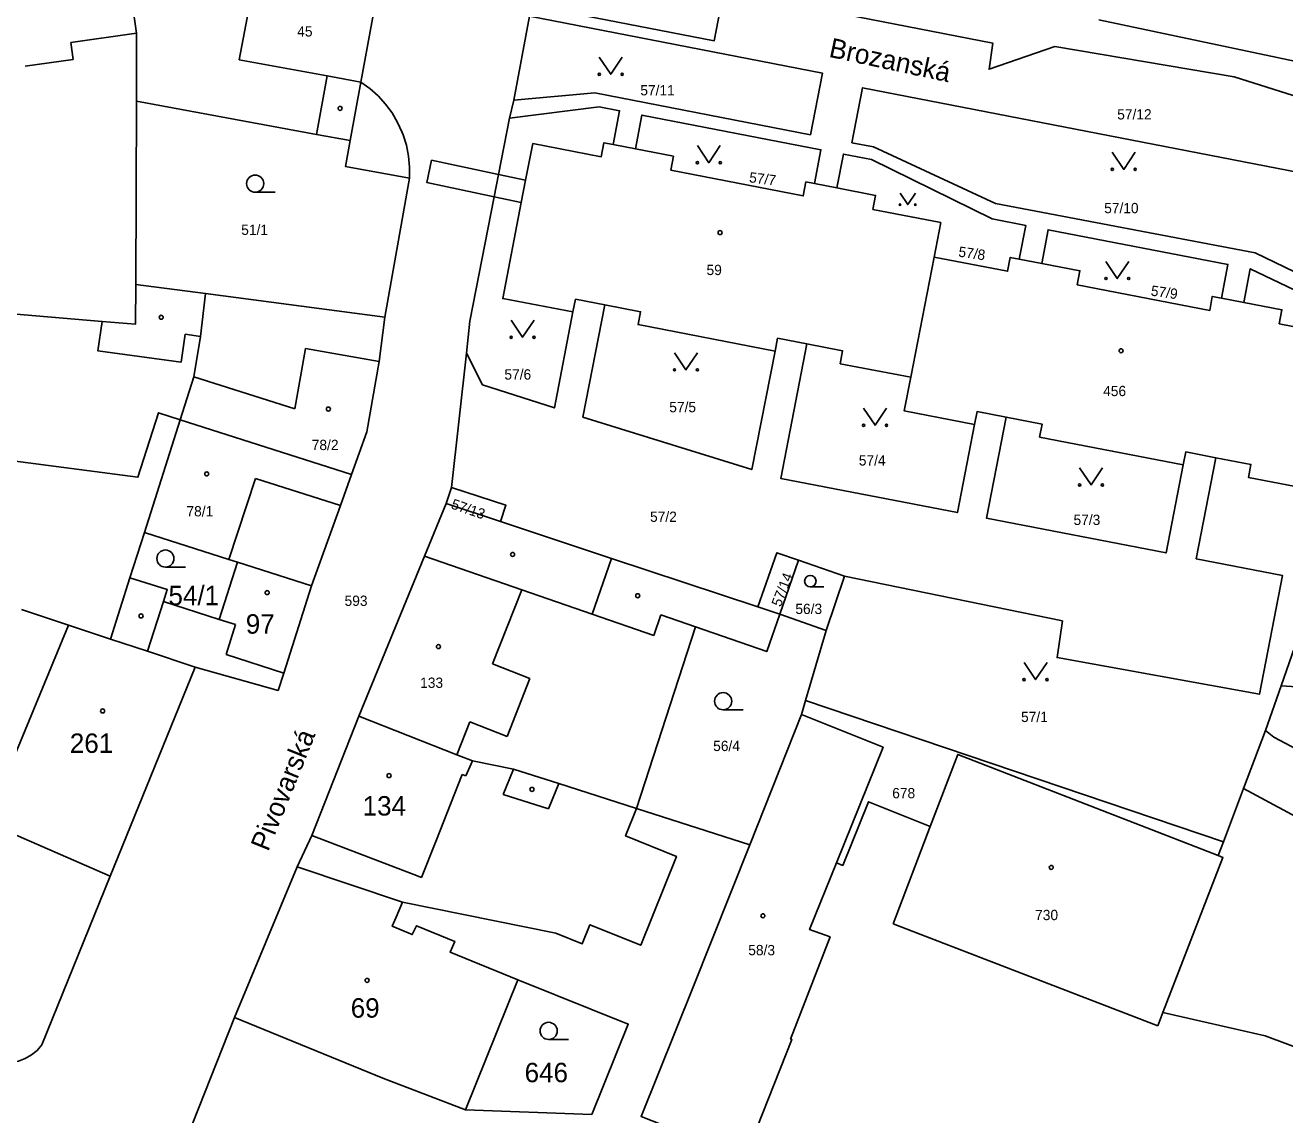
# Model space of a CAD drawing. Extents: x -758582 to -751794, y -998770 to -994350.
# Drawn here: x -755710.1 to -755599.9, y -995827 to -995731.7 of the extents above; entities that cross this region are included whole.
import ezdxf

# ---------------------------------------------------------------- set-up
doc = ezdxf.new("R2010")
doc.units = 0
for name, color, linetype in [('Hranice parcel', 7, 'Continuous'), ('Parcelní čísla', 7, 'Continuous'), ('Pop  PČ popisy', 7, 'Continuous'), ('Vnitřní kresba', 7, 'Continuous'), ('Věcná břemena k části', 7, 'Continuous'), ('Značky budov', 7, 'Continuous'), ('Značky kultur', 7, 'Continuous')]:
    doc.layers.add(name, color=color, linetype=linetype)

msp = doc.modelspace()

# ---------------------------------------------------------------- linework, layer by layer
at = {"layer": 'Hranice parcel'}
for p, q in [((-755680.76, -995736.69), (-755679.1, -995727.64)), ((-755666.01, -995730.92), (-755667.39, -995738.27)), ((-755700.44, -995754.38), (-755700.4, -995738.36)), ((-755667.39, -995738.27), (-755667.76, -995739.85)), ((-755656.75, -995742.53), (-755658.71, -995742.14)), ((-755678.66, -995757.24), (-755676.51, -995745.09)), ((-755639.13, -995745.94), (-755641.09, -995745.56)), ((-755632.66, -995762.51), (-755630.63, -995752)), ((-755621.21, -995752.55), (-755623.18, -995752.17)), ((-755603.54, -995755.96), (-755605.5, -995755.58)), ((-755715.41, -995756.62), (-755703.4, -995757.63)), ((-755671.53, -995760.39), (-755672.83, -995772.14)), ((-755696.56, -995766.23), (-755699.7, -995776.09)), ((-755681.58, -995771.01), (-755696.56, -995766.23)), ((-755673.3, -995773.56), (-755672.83, -995772.14)), ((-755668.55, -995775.13), (-755673.3, -995773.56)), ((-755700.96, -995780.05), (-755699.7, -995776.09)), ((-755691.55, -995778.69), (-755685.07, -995780.76)), ((-755642.49, -995778.52), (-755644.13, -995783.24)), ((-755638.45, -995779.92), (-755642.49, -995778.52)), ((-755596.45, -995778.47), (-755600.27, -995789.5)), ((-755700.96, -995780.05), (-755702.67, -995785.41)), ((-755640.06, -995784.65), (-755638.45, -995779.92)), ((-755644.13, -995783.24), (-755646.04, -995782.58)), ((-755644.13, -995783.24), (-755640.06, -995784.65)), ((-755641.86, -995790.79), (-755640.06, -995784.65)), ((-755702.69, -995806.16), (-755695.27, -995787.86)), ((-755601.63, -995793.41), (-755600.27, -995789.5)), ((-755642.21, -995792), (-755641.86, -995790.79)), ((-755641.86, -995790.79), (-755605.32, -995803.16)), ((-755642.21, -995792), (-755646.75, -995803.42)), ((-755603.55, -995798.48), (-755601.63, -995793.41)), ((-755605.32, -995803.16), (-755603.55, -995798.48)), ((-755584.98, -995808.56), (-755603.55, -995798.48)), ((-755646.75, -995803.42), (-755656.65, -995800.23)), ((-755634.2, -995810.32), (-755630.97, -995801.82)), ((-755605.32, -995803.16), (-755605.77, -995804.36)), ((-755686.35, -995805.35), (-755691.81, -995818.51)), ((-755677.13, -995808.42), (-755686.35, -995805.35)), ((-755708.67, -995820.92), (-755702.69, -995806.16)), ((-755611.06, -995819.25), (-755634.2, -995810.32)), ((-755671.62, -995826.6), (-755667.03, -995815.21)), ((-755610.61, -995818.09), (-755611.06, -995819.25))]:
    msp.add_line(p, q, dxfattribs=at)
for points in [[(-755616.22, -995731.24), (-755584.47, -995737.95), (-755577.34, -995717.51)], [(-755701.66, -995723.31), (-755700.39, -995732.42), (-755700.4, -995738.36)], [(-755580.66, -995748.82), (-755579.74, -995745.65), (-755585.82, -995744.38), (-755590.08, -995740.75), (-755604.38, -995736.24), (-755620.07, -995733.57), (-755625.82, -995735.56), (-755625.48, -995733.29), (-755649.01, -995728.69), (-755649.85, -995733.07), (-755665.81, -995729.99)], [(-755667.39, -995738.27), (-755660.29, -995737.63), (-755641.44, -995741.29), (-755640.39, -995735.9), (-755666.01, -995730.92)], [(-755676.51, -995745.09), (-755676.5, -995744.12), (-755676.59, -995743.16), (-755676.78, -995742.22), (-755677.07, -995741.29), (-755677.14, -995741.1), (-755677.55, -995740.22), (-755678.03, -995739.39), (-755678.61, -995738.61), (-755679.26, -995737.9), (-755679.98, -995737.26), (-755680.76, -995736.69)], [(-755594.4, -995748.74), (-755593.78, -995745.56), (-755636.88, -995737.19), (-755637.81, -995742), (-755635.94, -995742.36), (-755625.25, -995747.31), (-755602.55, -995751.62), (-755595.59, -995754.97), (-755595.48, -995754.29)], [(-755700.4, -995738.36), (-755684.65, -995741.26), (-755681.7, -995741.8), (-755682.11, -995744.07), (-755676.51, -995745.09)], [(-755658.71, -995742.14), (-755658.14, -995739.2), (-755659.91, -995738.86), (-755667.76, -995739.85)], [(-755641.09, -995745.56), (-755640.52, -995742.61), (-755656.18, -995739.58), (-755656.75, -995742.53)], [(-755667.76, -995739.85), (-755668.72, -995744.76), (-755669.1, -995746.72), (-755671.22, -995757.61), (-755671.53, -995760.39)], [(-755658.71, -995742.14), (-755659.5, -995741.99), (-755659.74, -995743.22), (-755665.73, -995742.06), (-755666.35, -995745.26), (-755666.73, -995747.23), (-755668.35, -995755.62), (-755662.21, -995756.8)], [(-755641.09, -995745.56), (-755641.83, -995745.42), (-755642.07, -995746.65), (-755653.65, -995744.4), (-755653.42, -995743.17), (-755656.75, -995742.53)], [(-755623.18, -995752.17), (-755622.61, -995749.23), (-755625.55, -995748.66), (-755636.1, -995743.45), (-755638.56, -995742.98), (-755639.13, -995745.94)], [(-755630.63, -995752), (-755630.05, -995748.98), (-755635.98, -995747.83), (-755635.74, -995746.6), (-755639.13, -995745.94)], [(-755580.66, -995748.82), (-755587.69, -995757.83), (-755595.9, -995756.4), (-755602.97, -995753.01), (-755603.54, -995755.96)], [(-755605.5, -995755.58), (-755604.93, -995752.64), (-755620.65, -995749.6), (-755621.21, -995752.55)], [(-755623.18, -995752.17), (-755623.96, -995752.02), (-755624.2, -995753.24), (-755630.63, -995752)], [(-755605.5, -995755.58), (-755606.29, -995755.43), (-755606.52, -995756.66), (-755618.11, -995754.42), (-755617.87, -995753.19), (-755621.21, -995752.55)], [(-755700.44, -995754.38), (-755700.48, -995757.87), (-755703.4, -995757.63)], [(-755678.66, -995757.24), (-755694.34, -995755.18), (-755700.44, -995754.38)], [(-755662.21, -995756.8), (-755661.99, -995755.68), (-755659.44, -995756.17)], [(-755605.98, -995769.55), (-755602.92, -995770.14), (-755603.13, -995771.27), (-755597.04, -995772.44), (-755594.45, -995758.99), (-755600.44, -995757.83), (-755600.2, -995756.61), (-755603.54, -995755.96)], [(-755681.58, -995771.01), (-755680.25, -995767.29), (-755679.16, -995761.13), (-755678.66, -995757.24)], [(-755662.21, -995756.8), (-755663.83, -995765.19), (-755670.12, -995763.18), (-755671.53, -995760.39)], [(-755644.54, -995760.22), (-755646.57, -995770.58), (-755661.34, -995765.99), (-755659.44, -995756.17)], [(-755659.44, -995756.17), (-755656.3, -995756.78), (-755656.52, -995757.9), (-755644.54, -995760.22)], [(-755703.4, -995757.63), (-755703.76, -995760.2), (-755696.49, -995761.18), (-755696.12, -995758.75), (-755694.8, -995758.93)], [(-755694.8, -995758.93), (-755695.36, -995762.47), (-755696.56, -995766.23)], [(-755644.54, -995760.22), (-755644.32, -995759.09), (-755641.77, -995759.58)], [(-755627.09, -995766.64), (-755628.58, -995774.35), (-755644.04, -995771.36), (-755641.77, -995759.58)], [(-755641.77, -995759.58), (-755638.63, -995760.19), (-755638.84, -995761.32), (-755632.66, -995762.51)], [(-755632.66, -995762.51), (-755633.23, -995765.46), (-755627.09, -995766.64)], [(-755728.64, -995767.54), (-755700.26, -995771.25), (-755698.47, -995765.62), (-755696.56, -995766.23)], [(-755627.09, -995766.64), (-755626.87, -995765.51), (-755624.32, -995766)], [(-755608.83, -995770.17), (-755610.33, -995777.87), (-755626.04, -995774.84), (-755624.32, -995766)], [(-755624.32, -995766), (-755621.18, -995766.61), (-755621.4, -995767.74), (-755615.05, -995768.96), (-755608.83, -995770.17)], [(-755608.83, -995770.17), (-755608.61, -995769.04), (-755605.98, -995769.55)], [(-755605.98, -995769.55), (-755607.7, -995778.38), (-755600.16, -995779.85), (-755602.17, -995790.24), (-755619.87, -995787.03), (-755619.4, -995783.82), (-755638.45, -995779.92)], [(-755685.07, -995780.76), (-755682.56, -995773.74), (-755681.58, -995771.01)], [(-755672.83, -995772.14), (-755668.08, -995773.71), (-755668.55, -995775.13)], [(-755673.3, -995773.56), (-755675.19, -995778.16), (-755680.93, -995792.16)], [(-755646.04, -995782.58), (-755658.84, -995778.35), (-755668.55, -995775.13)], [(-755699.7, -995776.09), (-755692.31, -995778.45), (-755691.55, -995778.69)], [(-755646.04, -995782.58), (-755644.38, -995777.86), (-755642.49, -995778.52)], [(-755691.55, -995778.69), (-755693.15, -995783.69), (-755698.03, -995782.13), (-755697.7, -995781.09), (-755700.96, -995780.05)], [(-755695.27, -995787.86), (-755688, -995789.91), (-755687.51, -995788.39), (-755685.07, -995780.76)], [(-755702.67, -995785.41), (-755706.35, -995784.19), (-755710.44, -995782.83)], [(-755656.65, -995800.23), (-755651.49, -995784.34), (-755645.26, -995786.5), (-755644.13, -995783.24)], [(-755702.67, -995785.41), (-755699.42, -995786.48), (-755695.27, -995787.86)], [(-755600.27, -995789.5), (-755593.92, -995789.92), (-755582.21, -995803.41)], [(-755680.93, -995792.16), (-755685.05, -995802.61), (-755686.35, -995805.35)], [(-755680.93, -995792.16), (-755672.37, -995795.53), (-755671.01, -995796.07), (-755667.41, -995796.78), (-755663.44, -995798.04), (-755656.65, -995800.23)], [(-755639.17, -995804.99), (-755635.09, -995794.87), (-755642.21, -995792)], [(-755601.63, -995793.41), (-755600.92, -995793.98), (-755591.16, -995799.16), (-755582.21, -995803.41)], [(-755630.97, -995801.82), (-755628.56, -995795.51), (-755605.77, -995804.36)], [(-755702.69, -995806.16), (-755713.48, -995801.46), (-755717.47, -995799.72)], [(-755630.97, -995801.82), (-755636.37, -995799.65), (-755638.61, -995805.21), (-755639.17, -995804.99)], [(-755656.65, -995800.23), (-755657.61, -995802.63), (-755653.16, -995804.42), (-755656.28, -995812.2), (-755660.74, -995810.42), (-755661.4, -995812.07), (-755663.72, -995811.14), (-755677.13, -995808.42)], [(-755646.75, -995803.42), (-755651.74, -995815.92), (-755656.25, -995827.17), (-755647.14, -995830.77), (-755643.06, -995820.45), (-755643.18, -995820.41), (-755639.72, -995811.47), (-755641.52, -995810.83), (-755639.17, -995804.99)], [(-755605.77, -995804.36), (-755605.37, -995804.51), (-755610.61, -995818.09)], [(-755677.13, -995808.42), (-755677.67, -995809.73), (-755678.02, -995810.54), (-755676.27, -995811.27), (-755675.9, -995810.49), (-755672.56, -995811.86), (-755672.96, -995812.81), (-755667.03, -995815.21)], [(-755667.03, -995815.21), (-755657.38, -995819.09), (-755660.57, -995827.01), (-755671.62, -995826.6)], [(-755691.81, -995818.51), (-755696.52, -995830.39), (-755697.31, -995832.34)], [(-755671.62, -995826.6), (-755678.83, -995823.83), (-755691.81, -995818.51)], [(-755586.26, -995825.88), (-755601.67, -995820.12), (-755610.61, -995818.09)], [(-755712.85, -995822.36), (-755712.23, -995822.47), (-755711.6, -995822.49), (-755710.98, -995822.4), (-755710.71, -995822.33), (-755710.12, -995822.1), (-755709.58, -995821.79), (-755709.09, -995821.39), (-755708.67, -995820.92)]]:
    msp.add_lwpolyline(points, dxfattribs=at)
at = {"layer": 'Vnitřní kresba'}
for p, q in [((-755691.41, -995734.74), (-755689.66, -995725.61)), ((-755700.39, -995732.42), (-755706.13, -995733.22)), ((-755706.13, -995733.22), (-755705.93, -995734.71)), ((-755705.93, -995734.71), (-755710.14, -995735.29)), ((-755691.41, -995734.74), (-755683.71, -995736.15)), ((-755683.71, -995736.15), (-755684.65, -995741.26)), ((-755683.71, -995736.15), (-755680.76, -995736.69)), ((-755681.7, -995741.8), (-755680.76, -995736.69)), ((-755694.8, -995758.93), (-755694.34, -995755.18)), ((-755686.55, -995765.28), (-755685.61, -995759.99)), ((-755679.16, -995761.13), (-755685.61, -995759.99)), ((-755695.36, -995762.47), (-755686.55, -995765.28)), ((-755689.99, -995771.37), (-755692.31, -995778.45)), ((-755682.56, -995773.74), (-755689.99, -995771.37)), ((-755675.19, -995778.16), (-755666.68, -995781.1)), ((-755658.84, -995778.35), (-755660.53, -995783.23)), ((-755669.24, -995787.58), (-755666.68, -995781.1)), ((-755666.68, -995781.1), (-755660.53, -995783.23)), ((-755699.42, -995786.48), (-755698.03, -995782.13)), ((-755660.53, -995783.23), (-755655.14, -995785.1)), ((-755655.14, -995785.1), (-755654.52, -995783.3)), ((-755654.52, -995783.3), (-755651.49, -995784.34)), ((-755713.48, -995801.46), (-755706.35, -995784.19)), ((-755693.15, -995783.69), (-755691.72, -995784.15)), ((-755691.72, -995784.15), (-755692.56, -995786.77)), ((-755692.56, -995786.77), (-755687.51, -995788.39)), ((-755665.98, -995788.86), (-755669.24, -995787.58)), ((-755667.98, -995793.93), (-755665.98, -995788.86)), ((-755672.37, -995795.53), (-755671.23, -995792.65)), ((-755671.23, -995792.65), (-755667.98, -995793.93)), ((-755671.59, -995797.37), (-755671.01, -995796.07)), ((-755668.32, -995799.02), (-755667.41, -995796.78)), ((-755671.91, -995797.25), (-755674.22, -995803.13)), ((-755671.91, -995797.25), (-755671.59, -995797.37)), ((-755668.32, -995799.02), (-755664.34, -995800.27)), ((-755663.44, -995798.04), (-755664.34, -995800.27)), ((-755685.05, -995802.61), (-755676.13, -995806.02)), ((-755674.22, -995803.13), (-755675.47, -995806.28)), ((-755676.13, -995806.02), (-755675.47, -995806.28))]:
    msp.add_line(p, q, dxfattribs=at)
at = {"layer": 'Věcná břemena k části'}
msp.add_lwpolyline([(-755674.58, -995743.51), (-755675, -995745.46), (-755669.1, -995746.72), (-755666.73, -995747.23), (-755666.35, -995745.26), (-755668.72, -995744.76)], close=True, dxfattribs=at)
at = {"layer": 'Značky budov'}
for centre in [(-755682.58, -995738.99), (-755649.35, -995749.86), (-755698.23, -995757.26), (-755614.27, -995760.19), (-755683.61, -995765.29), (-755694.25, -995770.96), (-755667.49, -995778.01), (-755688.96, -995781.35), (-755656.55, -995781.62), (-755699.99, -995783.39), (-755673.98, -995786.07), (-755703.35, -995791.7), (-755678.3, -995797.36), (-755665.8, -995798.56), (-755620.38, -995805.39), (-755645.6, -995809.62), (-755680.22, -995815.27)]:
    msp.add_circle(centre, 0.175, dxfattribs=at)
at = {"layer": 'Značky kultur'}
for p, q in [((-755690.01, -995746.32), (-755688.26, -995746.32)), ((-755697.86, -995779.12), (-755696.11, -995779.12)), ((-755641.45, -995780.85), (-755640.27, -995780.85)), ((-755649.08, -995791.6), (-755647.33, -995791.6)), ((-755664.34, -995820.44), (-755662.59, -995820.44))]:
    msp.add_line(p, q, dxfattribs=at)
for points in [[(-755659.91, -995734.5), (-755658.91, -995736), (-755657.91, -995734.5)], [(-755651.33, -995742.24), (-755650.33, -995743.74), (-755649.33, -995742.24)], [(-755615.04, -995742.83), (-755614.04, -995744.33), (-755613.04, -995742.83)], [(-755633.6, -995746.4), (-755632.93, -995747.41), (-755632.26, -995746.4)], [(-755615.6, -995752.37), (-755614.6, -995753.87), (-755613.6, -995752.37)], [(-755667.62, -995757.51), (-755666.62, -995759.01), (-755665.62, -995757.51)], [(-755653.33, -995760.36), (-755652.33, -995761.86), (-755651.33, -995760.36)], [(-755636.79, -995765.21), (-755635.79, -995766.71), (-755634.79, -995765.21)], [(-755617.9, -995770.43), (-755616.9, -995771.93), (-755615.9, -995770.43)], [(-755622.75, -995787.46), (-755621.75, -995788.96), (-755620.75, -995787.46)]]:
    msp.add_lwpolyline(points, dxfattribs=at)
for centre, radius in [((-755659.91, -995736), 0.1), ((-755657.91, -995736), 0.1), ((-755651.33, -995743.74), 0.1), ((-755649.33, -995743.74), 0.1), ((-755690.01, -995745.57), 0.75), ((-755615.04, -995744.33), 0.1), ((-755613.04, -995744.33), 0.1), ((-755633.6, -995747.41), 0.067), ((-755632.26, -995747.41), 0.067), ((-755615.6, -995753.87), 0.1), ((-755613.6, -995753.87), 0.1), ((-755667.62, -995759.01), 0.1), ((-755665.62, -995759.01), 0.1), ((-755653.33, -995761.86), 0.1), ((-755651.33, -995761.86), 0.1), ((-755636.79, -995766.71), 0.1), ((-755634.79, -995766.71), 0.1), ((-755617.9, -995771.93), 0.1), ((-755615.9, -995771.93), 0.1), ((-755697.86, -995778.37), 0.75), ((-755641.45, -995780.35), 0.502), ((-755622.75, -995788.96), 0.1), ((-755620.75, -995788.96), 0.1), ((-755649.08, -995790.85), 0.75), ((-755664.34, -995819.69), 0.75)]:
    msp.add_circle(centre, radius, dxfattribs=at)

# ---------------------------------------------------------------- texts
at = {"layer": 'Parcelní čísla'}
for s, height, p in [('45', 0.9, (-755686.33, -995732.7)), ('57/11', 0.9, (-755656.32, -995737.85)), ('57/12', 0.9, (-755614.61, -995739.96)), ('57/10', 0.9, (-755615.75, -995748.16)), ('51/1', 0.9, (-755691.23, -995750.06)), ('59', 0.9, (-755650.53, -995753.57)), ('57/6', 0.9, (-755668.21, -995762.71)), ('456', 0.9, (-755615.84, -995764.16)), ('57/5', 0.9, (-755653.79, -995765.57)), ('78/2', 0.9, (-755685.06, -995768.88)), ('57/4', 0.9, (-755637.21, -995770.23)), ('78/1', 0.9, (-755696.02, -995774.68)), ('57/2', 0.9, (-755655.47, -995775.16)), ('57/3', 0.9, (-755618.43, -995775.43)), ('54/1', 1.7, (-755697.59, -995782.45)), ('593', 0.9, (-755682.19, -995782.51)), ('56/3', 0.9, (-755642.76, -995783.22)), ('97', 1.7, (-755690.83, -995784.94)), ('133', 0.9, (-755675.58, -995789.68)), ('57/1', 0.9, (-755623.02, -995792.67)), ('261', 1.7, (-755706.22, -995795.37)), ('56/4', 0.9, (-755649.95, -995795.21)), ('678', 0.9, (-755634.29, -995799.34)), ('134', 1.7, (-755680.61, -995800.85)), ('730', 0.9, (-755621.79, -995810)), ('58/3', 0.9, (-755646.88, -995813.07)), ('69', 1.7, (-755681.65, -995818.53)), ('646', 1.7, (-755666.44, -995824.18))]:
    msp.add_text(s, height=height, dxfattribs=at).set_placement(p)
for s, rotation, p in [('57/7', 353, (-755646.84, -995745.45)), ('57/8', 352, (-755628.54, -995751.95)), ('57/9', 352, (-755611.71, -995755.36)), ('57/13', 341, (-755672.94, -995773.97)), ('57/14', 69, (-755644.04, -995782.65))]:
    msp.add_text(s, height=0.9, rotation=rotation, dxfattribs=at).set_placement(p)
at = {"layer": 'Pop  PČ popisy'}
for s, rotation, p in [('Brozanská', 348, (-755639.9, -995734.47)), ('Pivovarská', 68, (-755688.88, -995804.06))]:
    msp.add_text(s, height=1.7, rotation=rotation, dxfattribs=at).set_placement(p)

doc.saveas('drawing.dxf')
